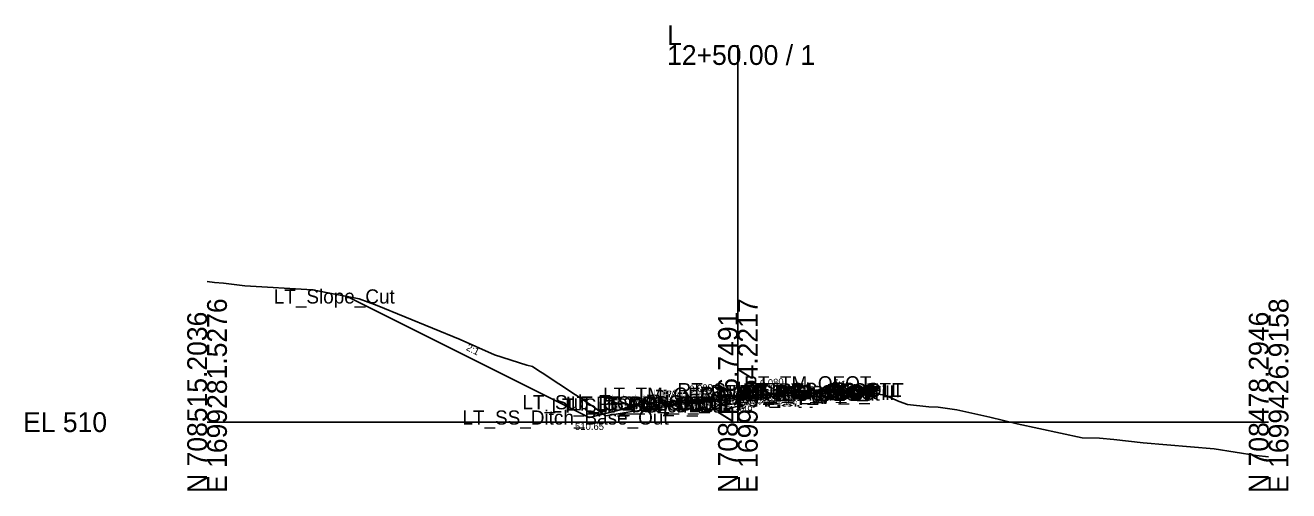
# Model space of a CAD drawing. Extents: x -63 to 1153, y -24 to 9522.
# Drawn here: x -25.7 to 152.8, y 2490.3 to 2556.1 of the extents above; entities that cross this region are included whole.
import ezdxf

# ---------------------------------------------------------------- set-up
doc = ezdxf.new("R2010")
doc.units = 0
for name, color, linetype in [('Default', 7, 'Continuous'), ('Exist Cross Section Cell', 7, 'Continuous'), ('Exist XS Center Line Elevation Label', 7, 'Continuous'), ('Exist XS Ground Line', 7, 'Continuous'), ('Prop CMT DNC', 7, 'Continuous'), ('Prop CMT Pvmt Course 1', 7, 'Continuous'), ('Prop CMT Pvmt Course 2', 7, 'Continuous'), ('Prop CMT Pvmt Surface', 7, 'Continuous'), ('Prop CMT Pvmt Surface Overlay', 7, 'Continuous'), ('Prop CMT Pvmt Surface Shoulder', 7, 'Continuous'), ('Prop CMT Shld Paved Course 1', 7, 'Continuous'), ('Prop CMT Shld Paved Course 2', 7, 'Continuous'), ('Prop CMT Slope Grass', 7, 'Continuous'), ('Prop CMT Subgrade Earthwork', 7, 'Continuous'), ('Prop XS Ditch Standard Text', 7, 'Continuous'), ('Prop XS Earthwork Shape', 7, 'Continuous'), ('Prop XS EOT Tick Mark', 7, 'Continuous'), ('Prop XS SE Text', 7, 'Continuous'), ('Prop XS Side Slope Text', 7, 'Continuous')]:
    doc.layers.add(name, color=color, linetype=linetype)

msp = doc.modelspace()

# ---------------------------------------------------------------- linework, layer by layer
at = {"layer": 'Exist Cross Section Cell'}
for p, q in [((75, 2500), (75, 2553.27)), ((0, 2500), (75, 2500)), ((75, 2500), (150, 2500))]:
    msp.add_line(p, q, dxfattribs=at)
at = {"layer": 'Exist XS Ground Line'}
msp.add_lwpolyline([(0, 2519.88), (1.05, 2519.74), (2.32, 2519.62), (5.31, 2519.25), (14.89, 2518.7), (21.47, 2517.43), (24.01, 2516.47), (35.78, 2511.69), (40.59, 2509.52), (45.18, 2508.03), (46, 2507.87), (46.86, 2507.26), (47.37, 2506.97), (54.41, 2502.3), (56.32, 2500.87), (58.94, 2501.3), (59.95, 2501.49), (62.48, 2501.77), (63.79, 2502.02), (65.64, 2502.37), (71.1, 2503.04), (75, 2503.49), (75.49, 2503.55), (79.93, 2503.93), (85.64, 2504.45), (91.22, 2503.99), (94.41, 2504.02), (95.76, 2503.79), (97.79, 2502.93), (98.97, 2502.5), (101.97, 2502.17), (103.3, 2502.1), (105.94, 2501.73), (110.6, 2500.68), (114.48, 2499.77), (123.65, 2497.79), (126.08, 2497.74), (128.14, 2497.56), (132.28, 2497.09), (142.29, 2496.23), (148.22, 2495.29), (150, 2495.09)], dxfattribs=at)
at = {"layer": 'Prop CMT Pvmt Course 1'}
for points in [[(75, 2503.69), (65, 2502.89)], [(65, 2502.64), (75, 2503.44)], [(75, 2503.69), (85, 2504.49)], [(85, 2504.24), (75, 2503.44)], [(75, 2503.57), (75, 2503.69)], [(75, 2503.57), (75, 2503.69)], [(75, 2503.44), (75, 2503.57), (75, 2503.57)], [(75, 2503.44), (75, 2503.57), (75, 2503.57)], [(85, 2504.49), (85, 2504.24)], [(65, 2502.89), (65, 2502.64)]]:
    msp.add_lwpolyline(points, dxfattribs=at)
at = {"layer": 'Prop CMT Pvmt Course 2'}
for points in [[(75, 2503.44), (65, 2502.64)], [(65, 2502.39), (75, 2503.19)], [(75, 2503.44), (85, 2504.24)], [(85, 2503.99), (75, 2503.19)], [(75, 2503.19), (75, 2503.44)], [(75, 2503.19), (75, 2503.44)], [(85, 2504.24), (85, 2503.99)], [(65, 2502.64), (65, 2502.39)]]:
    msp.add_lwpolyline(points, dxfattribs=at)
at = {"layer": 'Prop CMT Pvmt Surface'}
for points in [[(75, 2503.69), (65, 2502.89)], [(75, 2503.69), (85, 2504.49)]]:
    msp.add_lwpolyline(points, dxfattribs=at)
at = {"layer": 'Prop CMT Pvmt Surface Overlay'}
for points in [[(75, 2503.69), (65, 2502.89)], [(75, 2503.69), (85, 2504.49)]]:
    msp.add_lwpolyline(points, dxfattribs=at)
at = {"layer": 'Prop CMT Pvmt Surface Shoulder'}
for points in [[(85, 2504.49), (85.01, 2504.49)], [(65, 2502.89), (64.99, 2502.89)]]:
    msp.add_lwpolyline(points, dxfattribs=at)
at = {"layer": 'Prop CMT Shld Paved Course 1'}
for points in [[(85, 2504.49), (85.01, 2504.49), (85.24, 2504.26)], [(85, 2504.24), (85, 2504.49)], [(85.24, 2504.26), (85, 2504.24)], [(65, 2502.89), (64.99, 2502.89), (64.72, 2502.62)], [(64.72, 2502.62), (65, 2502.64)], [(65, 2502.64), (65, 2502.89)]]:
    msp.add_lwpolyline(points, dxfattribs=at)
at = {"layer": 'Prop CMT Shld Paved Course 2'}
for points in [[(85, 2504.24), (85.24, 2504.26)], [(85, 2503.99), (85, 2504.24)], [(85.47, 2504.03), (85, 2503.99)], [(85.24, 2504.26), (85.24, 2504.26)], [(85.24, 2504.26), (85.47, 2504.03)], [(64.72, 2502.62), (64.45, 2502.35)], [(64.45, 2502.35), (65, 2502.39)], [(65, 2502.64), (64.72, 2502.62)], [(64.72, 2502.62), (64.72, 2502.62)], [(65, 2502.39), (65, 2502.64)]]:
    msp.add_lwpolyline(points, dxfattribs=at)
at = {"layer": 'Prop CMT Slope Grass'}
for points in [[(62, 2502.65), (54, 2500.65), (19.79, 2517.76)], [(85.01, 2504.49), (88, 2504.55)], [(88, 2504.55), (89.78, 2504.11)], [(64.99, 2502.89), (62, 2502.65)]]:
    msp.add_lwpolyline(points, dxfattribs=at)
at = {"layer": 'Prop CMT Subgrade Earthwork'}
for points in [[(75, 2503.19), (65, 2502.39)], [(75, 2503.19), (85, 2503.99)], [(85, 2503.99), (85.47, 2504.03)], [(85.47, 2504.03), (85.95, 2504.51)], [(64.45, 2502.35), (63.98, 2502.81)], [(65, 2502.39), (64.45, 2502.35)]]:
    msp.add_lwpolyline(points, dxfattribs=at)
at = {"layer": 'Prop XS Earthwork Shape'}
for points in [[(54.41, 2502.3), (55.96, 2501.14), (54, 2500.65), (19.79, 2517.76), (21.47, 2517.43), (24.01, 2516.47), (35.78, 2511.69), (40.59, 2509.52), (45.18, 2508.03), (46, 2507.87), (46.86, 2507.26), (47.37, 2506.97)], [(85, 2503.99), (85.47, 2504.03), (85.88, 2504.43), (85.64, 2504.45), (79.93, 2503.93), (75.49, 2503.55), (75, 2503.49), (71.1, 2503.04), (67.3, 2502.58), (75, 2503.19)], [(88, 2504.55), (89.78, 2504.11), (85.88, 2504.43), (85.95, 2504.51)], [(63.98, 2502.81), (62, 2502.65), (55.96, 2501.14), (56.32, 2500.87), (58.94, 2501.3), (59.95, 2501.49), (62.48, 2501.77), (63.79, 2502.02), (65.64, 2502.37), (67.3, 2502.58), (65, 2502.39), (64.45, 2502.35)]]:
    msp.add_lwpolyline(points, close=True, dxfattribs=at)
at = {"layer": 'Prop XS EOT Tick Mark'}
for points in [[(85, 2504.49), (85, 2505.49)], [(65, 2502.89), (65, 2503.89)]]:
    msp.add_lwpolyline(points, dxfattribs=at)

# ---------------------------------------------------------------- texts
at = {"layer": 'Default'}
msp.add_text('-', height=0.0001, dxfattribs=at).set_placement((0, 2500))
at = {"layer": 'Exist Cross Section Cell'}
for s, p in [('L', (65, 2553.27)), ('12+50.00 / 1', (65, 2550.47)), ('EL 510', (-26, 2498.6))]:
    msp.add_text(s, height=2.8, dxfattribs=at).set_placement(p)
for s, p in [('E 1699281.5276', (2.8, 2490)), ('E 1699426.9158', (152.8, 2490)), ('E 1699354.2217', (77.8, 2490)), ('N 708515.2036', (0, 2490)), ('N 708496.7491', (75, 2490)), ('N 708478.2946', (150, 2490))]:
    msp.add_text(s, height=2.8, rotation=90, dxfattribs=at).set_placement(p)
at = {"layer": 'Exist XS Center Line Elevation Label'}
msp.add_text('513.49', height=1, dxfattribs=at).set_placement((72.99, 2501.29))
at = {"layer": 'Prop CMT DNC'}
for s, p in [('LT_Slope_Cut', (9.42, 2516.76)), ('LT_TM_OEOT', (55.94, 2502.89)), ('RT_Sub_Trench_Out_DLT', (66.47, 2503.51)), ('RT_Sub_Trench_Out', (69.63, 2503.03)), ('RT_PS2_Shelf_Out', (71.18, 2503.26)), ('RT_Sub_OEOT', (75.03, 2502.99)), ('RT_PV2_OEOT', (75.13, 2503.24)), ('RT_PS2_OEOP', (75.43, 2503.26)), ('RT_PV1_OEOT', (75.69, 2503.49)), ('RT_PS1_OEOP', (75.77, 2503.49)), ('RT_TM_OEOT', (75.9, 2504.49)), ('RT_GS_OS_CTL', (77.32, 2503.55)), ('RT_Slope_Fill', (80.25, 2503.11)), ('LT_Sub_Trench_Out_DLT', (44.55, 2501.81)), ('LT_Sub_Trench_Out', (48.65, 2501.35)), ('LT_PS2_Shelf_Out', (50.7, 2501.62)), ('LT_GS_OS_CTL', (51.37, 2501.65)), ('LT_PS2_OEOP', (54.95, 2501.62)), ('LT_Sub_OEOT', (55.08, 2501.39)), ('LT_PV2_OEOT', (55.17, 2501.64)), ('LT_PV1_OEOT', (55.74, 2501.89)), ('LT_PS1_OEOP', (55.79, 2501.89)), ('RT_PV1_OEEOP_W', (62.94, 2502.57)), ('LT_PV1_OEEOP_W', (62.98, 2502.57)), ('RT_Sub_OEEOP', (64.17, 2502.19)), ('LT_Sub_OEEOP', (64.21, 2502.19)), ('RT_PV2_OEEOP', (64.26, 2502.44)), ('LT_PV2_OEEOP', (64.31, 2502.44)), ('PV1_PGL_W', (67.58, 2502.57)), ('PV1_PGL', (69.47, 2502.69)), ('LT_SS_Ditch_Base_Out', (36.08, 2499.65))]:
    msp.add_text(s, height=2, dxfattribs=at).set_placement(p)
at = {"layer": 'Prop XS Ditch Standard Text'}
msp.add_text('510.65', height=1, dxfattribs=at).set_placement((51.99, 2498.9))
at = {"layer": 'Prop XS SE Text'}
for p in [(68.18, 2504.15), (78.18, 2504.95)]:
    msp.add_text('0.080', height=1, rotation=4.5739, dxfattribs=at).set_placement(p)
at = {"layer": 'Prop XS Side Slope Text'}
for s, rotation, p in [('2:1', 333.4349, (36.52, 2510.23)), ('4:1', 345.9638, (88.3, 2505.25)), ('4:1', 14.0362, (57.05, 2502.19))]:
    msp.add_text(s, height=1, rotation=rotation, dxfattribs=at).set_placement(p)

doc.saveas('drawing.dxf')
